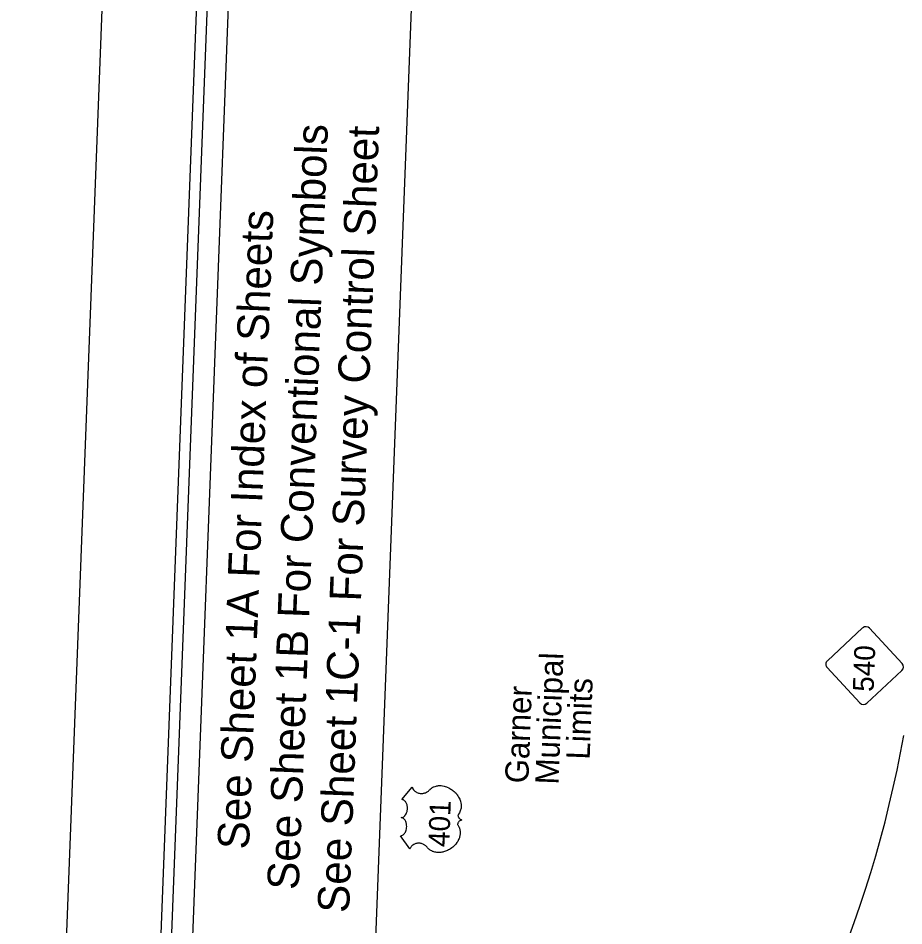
# Model space of a CAD drawing. Extents: x 2094564 to 2100382, y 679033 to 692366.
# Drawn here: x 2094564 to 2095618, y 683797 to 684877 of the extents above; entities that cross this region are included whole.
import ezdxf

# ---------------------------------------------------------------- set-up
doc = ezdxf.new("R2010")
doc.units = 0
for name, color, linetype in [('Default', 7, 'Continuous'), ('Pattern 17', 7, 'Continuous'), ('Prop Horizontal Alignment Curve and Spiral Data', 7, 'Continuous'), ('Prop Horizontal Alignment Direction Label', 7, 'Continuous'), ('Prop Horizontal Alignment Tick Label', 7, 'Continuous'), ('Prop Horizontal Alignment Tick Large', 7, 'Continuous')]:
    doc.layers.add(name, color=color, linetype=linetype)

msp = doc.modelspace()

# ---------------------------------------------------------------- linework, layer by layer
at = {"layer": 'Default'}
for p, q in [((2095058.6, 683962.5), (2095059.9, 683963)), ((2095059.9, 683963), (2095061.2, 683963.4)), ((2095061.2, 683963.4), (2095061.8, 683963.5)), ((2095061.8, 683963.5), (2095063.3, 683963.7)), ((2095063.3, 683963.7), (2095064, 683963.8)), ((2095064, 683963.8), (2095065.5, 683963.9)), ((2095065.5, 683963.9), (2095067.2, 683963.8)), ((2095067.2, 683963.8), (2095068.9, 683963.6)), ((2095068.9, 683963.6), (2095070.8, 683963.2)), ((2095070.8, 683963.2), (2095072, 683962.9)), ((2095020.2, 683947.3), (2095032.7, 683961.9)), ((2095032.7, 683961.9), (2095032.9, 683961.6)), ((2095032.9, 683961.6), (2095033.2, 683960.7)), ((2095033.2, 683960.7), (2095033.6, 683960.1)), ((2095033.6, 683960.1), (2095034.3, 683959)), ((2095034.3, 683959), (2095034.7, 683958.6)), ((2095034.7, 683958.6), (2095035.1, 683958.1)), ((2095035.1, 683958.1), (2095035.5, 683957.7)), ((2095035.5, 683957.7), (2095035.9, 683957.3)), ((2095035.9, 683957.3), (2095036.5, 683956.8)), ((2095036.5, 683956.8), (2095037.1, 683956.4)), ((2095037.1, 683956.4), (2095037.7, 683956)), ((2095037.7, 683956), (2095038.3, 683955.7)), ((2095038.3, 683955.7), (2095039.5, 683955.2)), ((2095039.5, 683955.2), (2095040.2, 683954.9)), ((2095040.2, 683954.9), (2095040.9, 683954.8)), ((2095040.9, 683954.8), (2095042.2, 683954.6)), ((2095042.2, 683954.6), (2095042.9, 683954.5)), ((2095042.9, 683954.5), (2095043.5, 683954.5)), ((2095043.5, 683954.5), (2095044.2, 683954.5)), ((2095044.2, 683954.5), (2095044.8, 683954.5)), ((2095044.8, 683954.5), (2095045.5, 683954.6)), ((2095045.5, 683954.6), (2095046.1, 683954.7)), ((2095046.1, 683954.7), (2095046.8, 683954.8)), ((2095046.8, 683954.8), (2095047.6, 683955.1)), ((2095047.6, 683955.1), (2095048.5, 683955.4)), ((2095048.5, 683955.4), (2095049.8, 683956)), ((2095049.8, 683956), (2095051.2, 683956.8)), ((2095051.2, 683956.8), (2095051.9, 683957.4)), ((2095051.9, 683957.4), (2095052.6, 683958)), ((2095052.6, 683958), (2095053.4, 683958.9)), ((2095053.4, 683958.9), (2095053.9, 683959.4)), ((2095053.9, 683959.4), (2095054.5, 683960)), ((2095054.5, 683960), (2095055.6, 683960.9)), ((2095055.6, 683960.9), (2095056.1, 683961.2)), ((2095056.1, 683961.2), (2095056.7, 683961.6)), ((2095056.7, 683961.6), (2095057.4, 683961.9)), ((2095057.4, 683961.9), (2095058, 683962.3)), ((2095058, 683962.3), (2095058.6, 683962.5)), ((2095072, 683962.9), (2095073.3, 683962.5)), ((2095073.3, 683962.5), (2095074.4, 683962.1)), ((2095074.4, 683962.1), (2095076.1, 683961.3)), ((2095076.1, 683961.3), (2095077.3, 683960.6)), ((2095077.3, 683960.6), (2095078.8, 683959.8)), ((2095078.8, 683959.8), (2095079.6, 683959.2)), ((2095079.6, 683959.2), (2095080.6, 683958.5)), ((2095080.6, 683958.5), (2095081.6, 683957.7)), ((2095081.6, 683957.7), (2095082.7, 683956.7)), ((2095082.7, 683956.7), (2095083.9, 683955.6)), ((2095083.9, 683955.6), (2095084.8, 683954.7)), ((2095084.8, 683954.7), (2095085.8, 683953.4)), ((2095085.8, 683953.4), (2095086.3, 683952.7)), ((2095086.3, 683952.7), (2095087.1, 683951.7)), ((2095020.6, 683947.3), (2095020.2, 683947.3)), ((2095021.1, 683947.2), (2095020.6, 683947.3)), ((2095021.7, 683947), (2095021.1, 683947.2)), ((2095022.3, 683946.8), (2095021.7, 683947)), ((2095022.8, 683946.5), (2095022.3, 683946.8)), ((2095023.3, 683946.1), (2095022.8, 683946.5)), ((2095024, 683945.5), (2095023.3, 683946.1)), ((2095024.6, 683944.8), (2095024, 683945.5)), ((2095025, 683944.2), (2095024.6, 683944.8)), ((2095025.5, 683943.4), (2095025, 683944.2)), ((2095025.9, 683942.5), (2095025.5, 683943.4)), ((2095026.2, 683941.8), (2095025.9, 683942.5)), ((2095026.5, 683940.9), (2095026.2, 683941.8)), ((2095087.1, 683951.7), (2095087.9, 683950.2)), ((2095087.9, 683950.2), (2095088.7, 683948.8)), ((2095088.7, 683948.8), (2095089.2, 683947.7)), ((2095089.2, 683947.7), (2095089.6, 683946.6)), ((2095089.6, 683946.6), (2095090.1, 683945.3)), ((2095090.1, 683945.3), (2095090.6, 683943)), ((2095090.6, 683943), (2095090.8, 683942.2)), ((2095090.8, 683942.2), (2095090.9, 683941.2)), ((2095025.5, 683930.3), (2095025.8, 683930.9)), ((2095025.8, 683930.9), (2095026, 683931.5)), ((2095026, 683931.5), (2095026.3, 683932.3)), ((2095026.3, 683932.3), (2095026.5, 683933.1)), ((2095026.7, 683940), (2095026.5, 683940.9)), ((2095026.5, 683933.1), (2095026.7, 683933.8)), ((2095026.8, 683939.3), (2095026.7, 683940)), ((2095026.7, 683933.8), (2095026.8, 683934.6)), ((2095026.9, 683938.5), (2095026.8, 683939.3)), ((2095026.8, 683934.6), (2095026.9, 683935.4)), ((2095027, 683937.7), (2095026.9, 683938.5)), ((2095026.9, 683935.4), (2095027, 683936.1)), ((2095027, 683936.9), (2095027, 683937.7)), ((2095027, 683936.1), (2095027, 683936.9)), ((2095088.8, 683931.5), (2095087.6, 683929.7)), ((2095089.4, 683932.6), (2095088.8, 683931.5)), ((2095089.9, 683933.7), (2095089.4, 683932.6)), ((2095090.3, 683934.9), (2095089.9, 683933.7)), ((2095090.6, 683936), (2095090.3, 683934.9)), ((2095090.8, 683937.1), (2095090.6, 683936)), ((2095090.9, 683938.3), (2095090.8, 683937.1)), ((2095090.9, 683941.2), (2095090.9, 683940.3)), ((2095090.9, 683940.3), (2095090.9, 683939.4)), ((2095090.9, 683939.4), (2095090.9, 683938.3)), ((2095020.2, 683925.7), (2095019.4, 683925.8)), ((2095019.4, 683925.8), (2095020.1, 683925.8)), ((2095020.1, 683925.8), (2095020.5, 683925.9)), ((2095020.6, 683925.6), (2095020.2, 683925.7)), ((2095020.5, 683925.9), (2095020.9, 683926)), ((2095021.5, 683925.2), (2095020.6, 683925.6)), ((2095020.9, 683926), (2095021.4, 683926.1)), ((2095021.4, 683926.1), (2095022, 683926.4)), ((2095021.9, 683925), (2095021.5, 683925.2)), ((2095022.3, 683924.7), (2095021.9, 683925)), ((2095022, 683926.4), (2095022.6, 683926.8)), ((2095023.1, 683924), (2095022.3, 683924.7)), ((2095022.6, 683926.8), (2095023.4, 683927.4)), ((2095023.8, 683923.2), (2095023.1, 683924)), ((2095023.4, 683927.4), (2095023.8, 683927.8)), ((2095023.8, 683927.8), (2095024.1, 683928.2)), ((2095024.2, 683922.6), (2095023.8, 683923.2)), ((2095024.1, 683928.2), (2095024.9, 683929.2)), ((2095024.7, 683921.9), (2095024.2, 683922.6)), ((2095025.1, 683921), (2095024.7, 683921.9)), ((2095024.9, 683929.2), (2095025.5, 683930.3)), ((2095025.4, 683920.1), (2095025.1, 683921)), ((2095025.7, 683919.3), (2095025.4, 683920.1)), ((2095087.2, 683928.9), (2095087.1, 683928.2)), ((2095087.1, 683928.2), (2095087.2, 683927.5)), ((2095087.4, 683919.8), (2095087.1, 683919.3)), ((2095087.3, 683929.2), (2095087.2, 683928.9)), ((2095087.2, 683927.5), (2095087.5, 683926.8)), ((2095087.6, 683929.7), (2095087.3, 683929.2)), ((2095087.8, 683920.4), (2095087.4, 683919.8)), ((2095087.5, 683926.8), (2095087.7, 683926.4)), ((2095087.7, 683926.4), (2095088, 683925.8)), ((2095088.2, 683921), (2095087.8, 683920.4)), ((2095088, 683925.8), (2095088.3, 683925.3)), ((2095088.7, 683921.4), (2095088.2, 683921)), ((2095088.3, 683925.3), (2095088.8, 683924.8)), ((2095089.3, 683921.9), (2095088.7, 683921.4)), ((2095088.8, 683924.8), (2095089.2, 683924.4)), ((2095089.2, 683924.4), (2095089.5, 683924.2)), ((2095089.8, 683922.2), (2095089.3, 683921.9)), ((2095089.5, 683924.2), (2095090.3, 683923.6)), ((2095090.4, 683922.5), (2095089.8, 683922.2)), ((2095090.3, 683923.6), (2095090.7, 683923.4)), ((2095091, 683922.8), (2095090.4, 683922.5)), ((2095090.7, 683923.4), (2095091.2, 683923.2)), ((2095091.9, 683923), (2095091, 683922.8)), ((2095091.2, 683923.2), (2095091.9, 683923)), ((2095024.6, 683908.6), (2095025.1, 683909.7)), ((2095025.1, 683909.7), (2095025.6, 683911)), ((2095025.6, 683911), (2095025.9, 683912.3)), ((2095025.8, 683918.5), (2095025.7, 683919.3)), ((2095026.1, 683916.7), (2095025.8, 683918.5)), ((2095025.9, 683912.3), (2095026.1, 683913.7)), ((2095026.2, 683915.2), (2095026.1, 683916.7)), ((2095026.1, 683913.7), (2095026.2, 683915.2)), ((2095086.8, 683918.4), (2095086.7, 683917.9)), ((2095086.7, 683917.9), (2095086.7, 683917.6)), ((2095086.7, 683917.6), (2095086.8, 683917.1)), ((2095086.9, 683918.9), (2095086.8, 683918.4)), ((2095086.8, 683917.1), (2095087.3, 683916.4)), ((2095087.1, 683919.3), (2095086.9, 683918.9)), ((2095087.3, 683916.4), (2095087.7, 683915.7)), ((2095087.7, 683915.7), (2095088.1, 683915)), ((2095088.1, 683915), (2095088.5, 683914.1)), ((2095088.5, 683914.1), (2095088.8, 683913.5)), ((2095088.8, 683913.5), (2095089, 683912.8)), ((2095089, 683912.8), (2095089.3, 683911.9)), ((2095089.3, 683911.9), (2095089.5, 683911)), ((2095089.5, 683911), (2095089.6, 683910)), ((2095089.6, 683910), (2095089.7, 683909.2)), ((2095089.7, 683909.2), (2095089.8, 683908.3)), ((2095018.6, 683904.2), (2095019.2, 683904.3)), ((2095030, 683888.7), (2095018.6, 683904.2)), ((2095019.2, 683904.3), (2095019.9, 683904.4)), ((2095019.9, 683904.4), (2095020.3, 683904.5)), ((2095020.3, 683904.5), (2095021.1, 683904.8)), ((2095021.1, 683904.8), (2095021.9, 683905.3)), ((2095021.9, 683905.3), (2095022.8, 683906.1)), ((2095022.8, 683906.1), (2095023.6, 683907)), ((2095023.6, 683907), (2095024, 683907.6)), ((2095024, 683907.6), (2095024.6, 683908.6)), ((2095087.3, 683898.4), (2095086.8, 683897.5)), ((2095087.9, 683899.8), (2095087.3, 683898.4)), ((2095088.4, 683900.8), (2095087.9, 683899.8)), ((2095088.8, 683901.8), (2095088.4, 683900.8)), ((2095089.1, 683902.8), (2095088.8, 683901.8)), ((2095089.3, 683903.8), (2095089.1, 683902.8)), ((2095089.5, 683904.9), (2095089.3, 683903.8)), ((2095089.6, 683905.8), (2095089.5, 683904.9)), ((2095089.7, 683906.6), (2095089.6, 683905.8)), ((2095089.8, 683907.4), (2095089.7, 683906.6)), ((2095089.8, 683908.3), (2095089.8, 683907.4)), ((2095030.2, 683889.2), (2095030, 683888.7)), ((2095030.6, 683889.9), (2095030.2, 683889.2)), ((2095031.1, 683890.6), (2095030.6, 683889.9)), ((2095031.5, 683891.2), (2095031.1, 683890.6)), ((2095032, 683891.9), (2095031.5, 683891.2)), ((2095032.7, 683892.5), (2095032, 683891.9)), ((2095033.5, 683893.1), (2095032.7, 683892.5)), ((2095034.5, 683893.7), (2095033.5, 683893.1)), ((2095035.5, 683894.3), (2095034.5, 683893.7)), ((2095036.2, 683894.6), (2095035.5, 683894.3)), ((2095037.2, 683894.9), (2095036.2, 683894.6)), ((2095038.1, 683895.1), (2095037.2, 683894.9)), ((2095039.1, 683895.3), (2095038.1, 683895.1)), ((2095040.1, 683895.4), (2095039.1, 683895.3)), ((2095041, 683895.4), (2095040.1, 683895.4)), ((2095042.1, 683895.3), (2095041, 683895.4)), ((2095043, 683895.1), (2095042.1, 683895.3)), ((2095043.9, 683894.9), (2095043, 683895.1)), ((2095044.6, 683894.7), (2095043.9, 683894.9)), ((2095045.6, 683894.3), (2095044.6, 683894.7)), ((2095046.2, 683894), (2095045.6, 683894.3)), ((2095047.1, 683893.5), (2095046.2, 683894)), ((2095047.7, 683893.2), (2095047.1, 683893.5)), ((2095048.3, 683892.7), (2095047.7, 683893.2)), ((2095049, 683892.1), (2095048.3, 683892.7)), ((2095049.5, 683891.7), (2095049, 683892.1)), ((2095050.4, 683890.7), (2095049.5, 683891.7)), ((2095050.9, 683890), (2095050.4, 683890.7)), ((2095051.7, 683889.2), (2095050.9, 683890)), ((2095052.5, 683888.4), (2095051.7, 683889.2)), ((2095053.2, 683887.7), (2095052.5, 683888.4)), ((2095054.1, 683887.1), (2095053.2, 683887.7)), ((2095077, 683887.8), (2095076, 683887.3)), ((2095078.2, 683888.6), (2095077, 683887.8)), ((2095080, 683889.9), (2095078.2, 683888.6)), ((2095081, 683890.7), (2095080, 683889.9)), ((2095082.5, 683892.1), (2095081, 683890.7)), ((2095083.4, 683893), (2095082.5, 683892.1)), ((2095084.5, 683894.3), (2095083.4, 683893)), ((2095085.8, 683896), (2095084.5, 683894.3)), ((2095086.8, 683897.5), (2095085.8, 683896)), ((2095054.9, 683886.6), (2095054.1, 683887.1)), ((2095055.9, 683886.1), (2095054.9, 683886.6)), ((2095056.9, 683885.6), (2095055.9, 683886.1)), ((2095057.8, 683885.3), (2095056.9, 683885.6)), ((2095058.6, 683885), (2095057.8, 683885.3)), ((2095059.6, 683884.7), (2095058.6, 683885)), ((2095060.9, 683884.5), (2095059.6, 683884.7)), ((2095062.1, 683884.3), (2095060.9, 683884.5)), ((2095063.1, 683884.2), (2095062.1, 683884.3)), ((2095064.3, 683884.2), (2095063.1, 683884.2)), ((2095065.6, 683884.3), (2095064.3, 683884.2)), ((2095066.9, 683884.4), (2095065.6, 683884.3)), ((2095067.8, 683884.5), (2095066.9, 683884.4)), ((2095069.1, 683884.8), (2095067.8, 683884.5)), ((2095069.9, 683884.9), (2095069.1, 683884.8)), ((2095071, 683885.3), (2095069.9, 683884.9)), ((2095072.3, 683885.7), (2095071, 683885.3)), ((2095073.6, 683886.2), (2095072.3, 683885.7)), ((2095074.6, 683886.6), (2095073.6, 683886.2)), ((2095076, 683887.3), (2095074.6, 683886.6))]:
    msp.add_line(p, q, dxfattribs=at)
at = {"layer": 'Pattern 17'}
for p, q in [((2095526.6, 684112.4), (2095568.6, 684151.4)), ((2095576.8, 684151.1), (2095615.8, 684109)), ((2095565.2, 684062.2), (2095526.3, 684104.2)), ((2095615.4, 684100.8), (2095573.4, 684061.9))]:
    msp.add_line(p, q, dxfattribs=at)
msp.add_lwpolyline([(2094975.9, 683430.3), (2095048.9, 685332.8), (2096016.8, 685295.7), (2096009.9, 685115.7), (2096680.3, 685090), (2096614.3, 683367.4)], close=True, dxfattribs=at)
for centre, start, end in [((2095572.6, 684147.1), 42.8037, 132.8037), ((2095530.5, 684108.2), 132.8037, 222.8037), ((2095611.5, 684105.1), 312.8037, 42.8037), ((2095569.5, 684066.1), 222.8037, 312.8037)]:
    msp.add_arc(centre, 5.78, start, end, dxfattribs=at)
at = {"layer": 'Prop Horizontal Alignment Direction Label'}
for points in [[(2095006.3, 690563.5), (2094722.6, 683168.8)], [(2095030.3, 690537.5), (2094758.2, 683442.8)]]:
    msp.add_lwpolyline(points, dxfattribs=at)
msp.add_arc((2094220.3, 684274.7), 1419.7, 322.7766, 349.8037, dxfattribs=at)
at = {"layer": 'Prop Horizontal Alignment Tick Label'}
msp.add_lwpolyline([(2099950.1, 682147.8), (2100269.5, 690474.2), (2094997.8, 690676.3), (2094678.5, 682349.9)], close=True, dxfattribs=at)
at = {"layer": 'Prop Horizontal Alignment Tick Large'}
msp.add_lwpolyline([(2094886.5, 690703.1), (2094563.9, 682289.3), (2100059.8, 682078.5), (2100382.4, 690492.3)], close=True, dxfattribs=at)

# ---------------------------------------------------------------- texts
at = {"layer": 'Default'}
msp.add_text('401', height=24.9, rotation=87.8037, dxfattribs=at).set_placement((2095076.6, 683890.4))
at = {"layer": 'Pattern 17'}
msp.add_text('540', height=24.79, rotation=87.8037, dxfattribs=at).set_placement((2095581.6, 684075.1))
at = {"layer": 'Prop Horizontal Alignment Curve and Spiral Data'}
for s, p in [('See Sheet 1B For Conventional Symbols', (2094897.6, 683839.4)), ('See Sheet 1C-1 For Survey Control Sheet', (2094957.5, 683812)), ('See Sheet 1A For Index of Sheets', (2094838.4, 683887.5))]:
    msp.add_text(s, height=37.5, rotation=87.8037, dxfattribs=at).set_placement(p)
at = {"layer": 'Prop Horizontal Alignment Direction Label'}
for s, p in [('Municipal', (2095206.7, 683964.8)), ('Garner', (2095170.8, 683966.2)), ('   Limits', (2095242.6, 683963.5))]:
    msp.add_text(s, height=27.78, rotation=87.8037, dxfattribs=at).set_placement(p)

doc.saveas('drawing.dxf')
